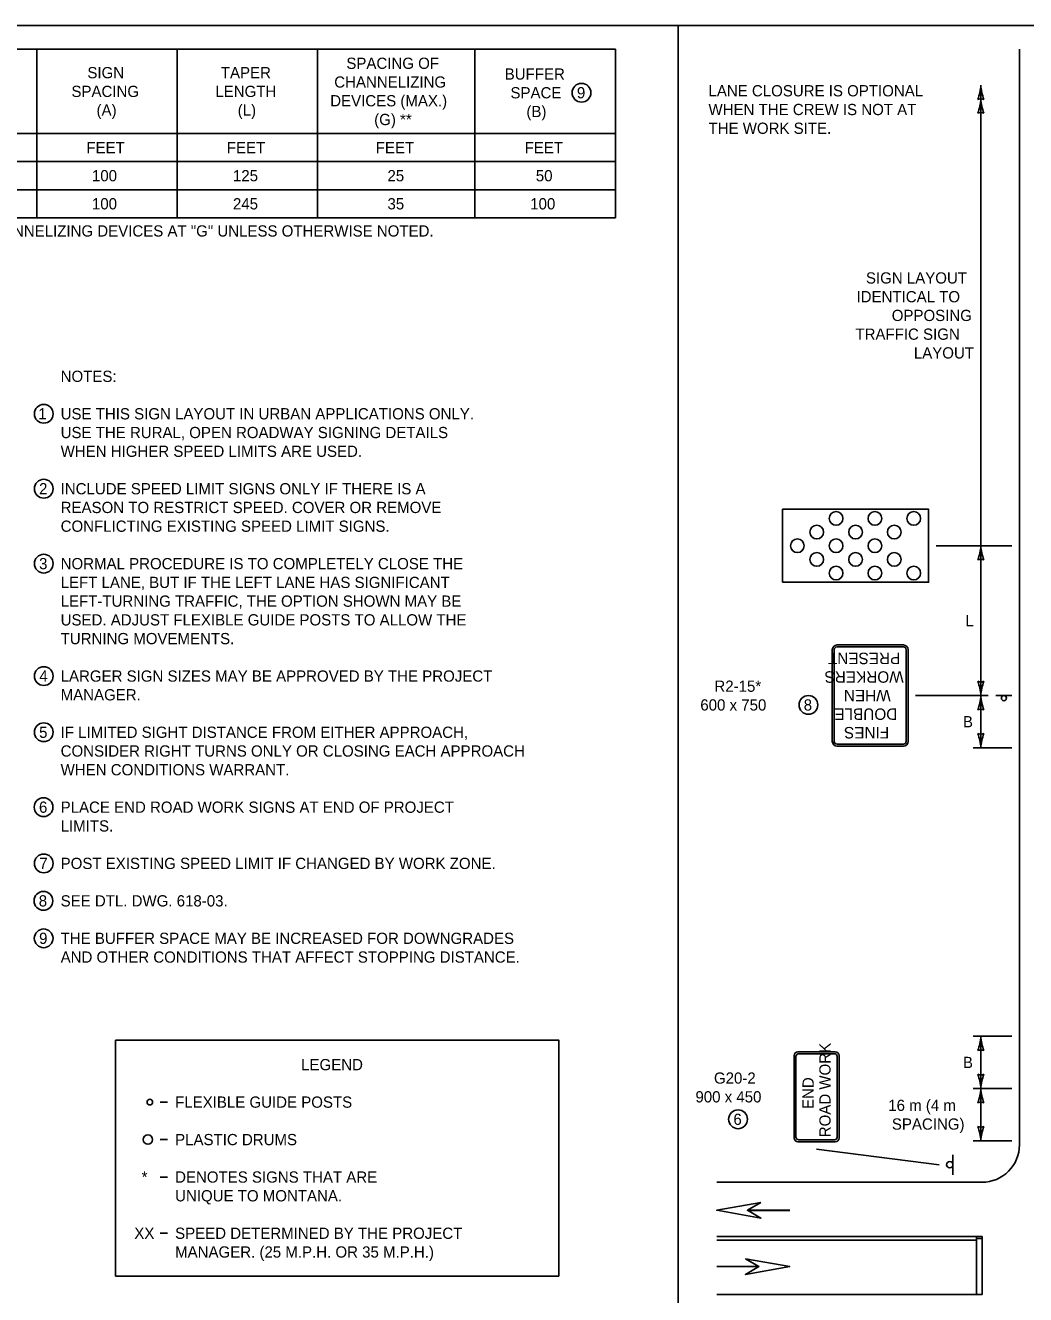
# Model space of a CAD drawing. Extents: x 49991.4 to 50021, y 49987.6 to 50011.4.
# Drawn here: x 50004.58 to 50009.92, y 49992.22 to 49999 of the extents above; entities that cross this region are included whole.
import ezdxf

# ---------------------------------------------------------------- set-up
doc = ezdxf.new("R2010")
doc.units = 0
for name, color, linetype in [('Level 1', 7, 'Continuous'), ('Level 2', 7, 'Continuous'), ('Level 3', 7, 'Continuous')]:
    doc.layers.add(name, color=color, linetype=linetype)

msp = doc.modelspace()

# ---------------------------------------------------------------- linework, layer by layer
at = {"layer": 'Level 1'}
for p, q in [((50008.0668, 49998.9992), (50008.0668, 49987.7988)), ((50009.889, 49993.024), (50009.889, 49998.8719)), ((50008.915, 49995.6917), (50009.2694, 49995.6917)), ((50008.915, 49995.6812), (50009.2694, 49995.6812)), ((50008.8896, 49995.177), (50008.8896, 49995.6664)), ((50008.9002, 49995.177), (50008.9002, 49995.6664)), ((50009.2842, 49995.6664), (50009.2842, 49995.177)), ((50009.2947, 49995.6664), (50009.2947, 49995.177)), ((50009.7626, 49995.4217), (50009.849, 49995.4217)), ((50009.2694, 49995.1622), (50008.915, 49995.1622)), ((50009.2694, 49995.1517), (50008.915, 49995.1517)), ((50009.0922, 49995.1517), (50009.0922, 49995.1517)), ((50008.7057, 49993.52), (50008.9057, 49993.52)), ((50008.7107, 49993.51), (50008.9007, 49993.51)), ((50008.6857, 49993.5), (50008.6857, 49993.06)), ((50008.6957, 49993.495), (50008.6957, 49993.065)), ((50008.9157, 49993.495), (50008.9157, 49993.065)), ((50008.9258, 49993.4999), (50008.9258, 49993.0599)), ((50008.9057, 49993.04), (50008.7057, 49993.04)), ((50008.9007, 49993.05), (50008.7107, 49993.05)), ((50009.5339, 49992.9706), (50009.5339, 49992.864)), ((50009.689, 49992.824), (50008.2722, 49992.824)), ((50008.6623, 49992.6741), (50008.4364, 49992.6741)), ((50008.6623, 49992.6737), (50008.4364, 49992.6737)), ((50009.689, 49992.5341), (50008.2722, 49992.5341)), ((50009.659, 49992.5141), (50008.2722, 49992.5141)), ((50009.659, 49992.5341), (50009.659, 49992.224)), ((50009.659, 49992.5241), (50009.689, 49992.5241)), ((50009.689, 49992.5341), (50009.689, 49992.224)), ((50008.2722, 49992.3741), (50008.4981, 49992.3741)), ((50008.2722, 49992.3737), (50008.4981, 49992.3737)), ((50009.689, 49992.224), (50008.2722, 49992.224))]:
    msp.add_line(p, q, dxfattribs=at)
for points in [[(49999.3835, 49998.9992), (50016.7501, 49998.9992), (50016.7501, 49987.7988), (49999.3835, 49987.7988)], [(50008.6239, 49996.0267), (50009.4036, 49996.0267), (50009.4036, 49996.4167), (50008.6239, 49996.4167)], [(50008.6239, 49996.0267), (50009.4036, 49996.0267), (50009.4036, 49996.4167), (50008.6239, 49996.4167)], [(50008.5087, 49992.7157), (50008.2722, 49992.6741), (50008.5087, 49992.6321), (50008.4365, 49992.6741)], [(50008.4258, 49992.4157), (50008.6623, 49992.3741), (50008.4258, 49992.3321), (50008.498, 49992.3741)]]:
    msp.add_lwpolyline(points, close=True, dxfattribs=at)
for points in [[(50009.689, 49992.5341), (50009.659, 49992.5341), (50009.659, 49992.5241), (50009.689, 49992.5241), (50009.689, 49992.5341)], [(50009.659, 49992.224), (50009.689, 49992.224), (50009.689, 49992.5241), (50009.659, 49992.5241), (50009.659, 49992.224)]]:
    msp.add_lwpolyline(points, dxfattribs=at)
for centre, radius in [((50008.91, 49996.3677), 0.0366), ((50008.91, 49996.3677), 0.0366), ((50009.1171, 49996.3677), 0.0366), ((50009.1171, 49996.3677), 0.0366), ((50009.3243, 49996.3677), 0.0366), ((50009.3243, 49996.3677), 0.0366), ((50008.8065, 49996.2946), 0.0366), ((50008.8065, 49996.2946), 0.0366), ((50009.0136, 49996.2946), 0.0366), ((50009.0136, 49996.2946), 0.0366), ((50009.2207, 49996.2946), 0.0366), ((50009.2207, 49996.2946), 0.0366), ((50008.7029, 49996.2215), 0.0366), ((50008.7029, 49996.2215), 0.0366), ((50008.91, 49996.2215), 0.0366), ((50008.91, 49996.2215), 0.0366), ((50009.1171, 49996.2215), 0.0366), ((50009.1171, 49996.2215), 0.0366), ((50008.8065, 49996.1484), 0.0366), ((50008.8065, 49996.1484), 0.0366), ((50009.0136, 49996.1484), 0.0366), ((50009.0136, 49996.1484), 0.0366), ((50009.2207, 49996.1484), 0.0366), ((50009.2207, 49996.1484), 0.0366), ((50008.91, 49996.0753), 0.0366), ((50008.91, 49996.0753), 0.0366), ((50009.1171, 49996.0753), 0.0366), ((50009.1171, 49996.0753), 0.0366), ((50009.3243, 49996.0753), 0.0366), ((50009.3243, 49996.0753), 0.0366), ((50009.8059, 49995.4081), 0.0137), ((50005.2457, 49993.2516), 0.015), ((50005.2357, 49993.0516), 0.025), ((50009.5171, 49992.9173), 0.0169)]:
    msp.add_circle(centre, radius, dxfattribs=at)
for centre, radius, start, end in [((50008.915, 49995.6664), 0.0253, 90, 180), ((50008.915, 49995.6664), 0.0148, 90, 180), ((50009.2694, 49995.6664), 0.0253, 360, 90), ((50009.2694, 49995.6664), 0.0148, 360, 90), ((50008.915, 49995.177), 0.0253, 180, 270), ((50008.915, 49995.177), 0.0148, 180, 270), ((50009.2694, 49995.177), 0.0148, 270, 360), ((50009.2694, 49995.177), 0.0253, 270, 360), ((50008.7057, 49993.5), 0.02, 90, 180), ((50008.7107, 49993.495), 0.015, 90, 180), ((50008.9007, 49993.495), 0.015, 360, 90), ((50008.9057, 49993.4999), 0.02, 360, 90), ((50005.2357, 49993.0516), 0.025, 360, 180), ((50005.2357, 49993.0516), 0.025, 180, 0), ((50008.7057, 49993.06), 0.02, 180, 270), ((50008.7107, 49993.065), 0.015, 180, 270), ((50008.9007, 49993.065), 0.015, 270, 360), ((50008.9057, 49993.0599), 0.02, 270, 360), ((50009.689, 49993.024), 0.2, 270, 0.00074)]:
    msp.add_arc(centre, radius, start, end, dxfattribs=at)
at = {"layer": 'Level 2'}
for p, q in [((50003.8015, 49998.8719), (50007.7315, 49998.8719)), ((50004.6415, 49998.8719), (50004.6415, 49997.9719)), ((50005.3915, 49998.8719), (50005.3915, 49997.9719)), ((50006.1415, 49998.8719), (50006.1415, 49997.9719)), ((50006.9815, 49998.8719), (50006.9815, 49997.9719)), ((50007.7315, 49998.8719), (50007.7315, 49997.9719)), ((50003.8015, 49998.4219), (50007.7315, 49998.4219)), ((50003.8015, 49998.2719), (50007.7315, 49998.2719)), ((50003.8015, 49998.1219), (50007.7315, 49998.1219)), ((50003.8015, 49997.9719), (50007.7315, 49997.9719)), ((50005.0629, 49992.3216), (50005.0629, 49993.5816)), ((50005.3407, 49993.2516), (50005.3007, 49993.2516)), ((50005.3007, 49993.0516), (50005.3407, 49993.0516)), ((50005.3407, 49992.8516), (50005.3007, 49992.8516)), ((50005.3407, 49992.5516), (50005.3007, 49992.5516)), ((50007.4297, 49992.3216), (50005.0629, 49992.3216))]:
    msp.add_line(p, q, dxfattribs=at)
msp.add_lwpolyline([(50005.0629, 49993.5816), (50007.4297, 49993.5816), (50007.4297, 49992.3216)], dxfattribs=at)
for centre in [(50007.5506, 49998.6397), (50004.6794, 49996.9259), (50004.6794, 49996.5259), (50004.6794, 49996.1259), (50004.6794, 49995.5259), (50008.762, 49995.3718), (50004.6794, 49995.2259), (50004.6783, 49994.8259), (50004.6794, 49994.5259), (50004.6776, 49994.3259), (50004.6789, 49994.1259), (50008.3863, 49993.1599)]:
    msp.add_circle(centre, 0.0501, dxfattribs=at)
at = {"layer": 'Level 3'}
for p, q in [((50009.6826, 49996.2217), (50009.6826, 49998.6802)), ((50009.4436, 49996.2217), (50009.849, 49996.2217)), ((50009.6826, 49995.4217), (50009.6826, 49996.2217)), ((50009.3347, 49995.4217), (50009.4587, 49995.4217)), ((50009.7226, 49995.4217), (50009.4587, 49995.4217)), ((50009.7226, 49995.4217), (50009.6426, 49995.4217)), ((50009.6826, 49995.1428), (50009.6826, 49995.4217)), ((50009.849, 49995.1428), (50009.6426, 49995.1428)), ((50009.849, 49993.6029), (50009.6426, 49993.6029)), ((50009.6826, 49993.3239), (50009.6826, 49993.6029)), ((50009.849, 49993.3239), (50009.6426, 49993.3239)), ((50009.6826, 49993.045), (50009.6826, 49993.3239)), ((50009.849, 49993.045), (50009.6426, 49993.045)), ((50008.8057, 49993), (50009.4602, 49992.9173))]:
    msp.add_line(p, q, dxfattribs=at)
for centre, radius, start, end in [((50009.4605, 49998.6894), 0.2223, 337.45601, 357.63952), ((50009.9153, 49998.6917), 0.233, 182.82731, 202.07716), ((50009.6826, 49998.552), 0.0548, 72.13882, 107.86118), ((50009.4605, 49998.616), 0.2223, 337.45601, 357.63952), ((50009.9153, 49998.6183), 0.233, 182.82731, 202.07716), ((50009.6826, 49998.4786), 0.0548, 72.13882, 107.86118), ((50009.4605, 49996.2309), 0.2223, 337.45601, 357.63952), ((50009.9153, 49996.2332), 0.233, 182.82731, 202.07716), ((50009.6826, 49996.0935), 0.0548, 72.13882, 107.86118), ((50009.6826, 49995.5499), 0.0548, 252.13882, 287.86118), ((50009.4499, 49995.4102), 0.233, 2.82731, 22.07716), ((50009.9048, 49995.4125), 0.2223, 157.45601, 177.63952), ((50009.4605, 49995.4309), 0.2223, 337.45601, 357.63952), ((50009.9153, 49995.4332), 0.233, 182.82731, 202.07716), ((50009.6826, 49995.2935), 0.0548, 72.13882, 107.86118), ((50009.6826, 49995.271), 0.0548, 252.13882, 287.86118), ((50009.4499, 49995.1313), 0.233, 2.82731, 22.07716), ((50009.9048, 49995.1336), 0.2223, 157.45601, 177.63952), ((50009.4605, 49993.612), 0.2223, 337.45601, 357.63952), ((50009.9153, 49993.6144), 0.233, 182.82731, 202.07716), ((50009.6826, 49993.4746), 0.0548, 72.13882, 107.86118), ((50009.6826, 49993.4522), 0.0548, 252.13882, 287.86118), ((50009.4499, 49993.3125), 0.233, 2.82731, 22.07716), ((50009.9048, 49993.3148), 0.2223, 157.45601, 177.63952), ((50009.4605, 49993.3331), 0.2223, 337.45601, 357.63952), ((50009.9153, 49993.3354), 0.233, 182.82731, 202.07716), ((50009.6826, 49993.1957), 0.0548, 72.13882, 107.86118), ((50009.6826, 49993.1733), 0.0548, 252.13882, 287.86118), ((50009.4499, 49993.0335), 0.233, 2.82731, 22.07716), ((50009.9048, 49993.0359), 0.2223, 157.45601, 177.63952)]:
    msp.add_arc(centre, radius, start, end, dxfattribs=at)

# ---------------------------------------------------------------- texts
at = {"layer": 'Level 1'}
for s, height, rotation, p in [('PRESENT', 0.06118, 180, (50009.2526, 49995.6506)), ('WORKERS', 0.06118, 180, (50009.2707, 49995.5514)), ('WHEN', 0.06118, 180, (50009.2013, 49995.4523)), ('DOUBLE', 0.06118, 180, (50009.2368, 49995.3531)), ('FINES', 0.06118, 180, (50009.1933, 49995.254)), ('ROAD WORK', 0.06, 90, (50008.8804, 49993.0641)), ('END', 0.06, 90, (50008.7904, 49993.2148))]:
    msp.add_text(s, height=height, rotation=rotation, dxfattribs=at).set_placement(p)
at = {"layer": 'Level 2'}
for s, height, p in [('SPACING OF', 0.06, (50006.295, 49998.7669)), ('SIGN', 0.06, (50004.9122, 49998.7169)), ('TAPER', 0.06, (50005.6248, 49998.7169)), ('CHANNELIZING', 0.06, (50006.2303, 49998.6669)), ('BUFFER', 0.06, (50007.1405, 49998.7096)), ('SPACING', 0.06, (50004.8271, 49998.6169)), ('LENGTH', 0.06, (50005.5956, 49998.6169)), ('SPACE', 0.06, (50007.1713, 49998.6096)), ('9', 0.06, (50007.526, 49998.6097)), ('LANE CLOSURE IS OPTIONAL', 0.06, (50008.2286, 49998.6202)), ('DEVICES (MAX.)', 0.06, (50006.2089, 49998.5669)), ('(A)', 0.06, (50004.9612, 49998.5169)), ('(L)', 0.06, (50005.7149, 49998.5169)), ('(G) **', 0.06, (50006.4436, 49998.4669)), ('(B)', 0.06, (50007.2564, 49998.5096)), ('WHEN THE CREW IS NOT AT', 0.06, (50008.2286, 49998.5202)), ('THE WORK SITE.', 0.06, (50008.2286, 49998.4202)), ('FEET', 0.06, (50004.9069, 49998.3169)), ('FEET', 0.06, (50005.6569, 49998.3169)), ('FEET', 0.06, (50006.4519, 49998.3169)), ('FEET', 0.06, (50007.2469, 49998.3169)), ('100', 0.06, (50004.9366, 49998.1669)), ('125', 0.06, (50005.6895, 49998.1669)), ('25', 0.06, (50006.5145, 49998.1669)), ('50', 0.06, (50007.3066, 49998.1669)), ('100', 0.06, (50004.9366, 49998.0169)), ('245', 0.06, (50005.6895, 49998.0169)), ('35', 0.06, (50006.5145, 49998.0169)), ('100', 0.06, (50007.2766, 49998.0169)), ('** SPACE ALL CHANNELIZING DEVICES AT "G" UNLESS OTHERWISE NOTED.', 0.06, (50003.8015, 49997.8719)), ('SIGN LAYOUT', 0.06, (50009.0692, 49997.621)), ('IDENTICAL TO', 0.06, (50009.0189, 49997.521)), ('OPPOSING', 0.06, (50009.207, 49997.421)), ('TRAFFIC SIGN', 0.06, (50009.0131, 49997.321)), ('LAYOUT', 0.06, (50009.3251, 49997.221)), ('NOTES:', 0.06, (50004.7695, 49997.0959)), ('1', 0.06, (50004.6502, 49996.896)), ('USE THIS SIGN LAYOUT IN URBAN APPLICATIONS ONLY.', 0.06, (50004.7695, 49996.8959)), ('USE THE RURAL, OPEN ROADWAY SIGNING DETAILS', 0.06, (50004.7695, 49996.7959)), ('WHEN HIGHER SPEED LIMITS ARE USED.', 0.06, (50004.7695, 49996.6959)), ('2', 0.06, (50004.6543, 49996.4959)), ('INCLUDE SPEED LIMIT SIGNS ONLY IF THERE IS A', 0.06, (50004.7695, 49996.4959)), ('REASON TO RESTRICT SPEED. COVER OR REMOVE', 0.06, (50004.7695, 49996.3959)), ('CONFLICTING EXISTING SPEED LIMIT SIGNS.', 0.06, (50004.7695, 49996.2959)), ('3', 0.06, (50004.6542, 49996.0959)), ('NORMAL PROCEDURE IS TO COMPLETELY CLOSE THE', 0.06, (50004.7695, 49996.0959)), ('LEFT LANE, BUT IF THE LEFT LANE HAS SIGNIFICANT ', 0.06, (50004.7695, 49995.9959)), ('LEFT-TURNING TRAFFIC, THE OPTION SHOWN MAY BE', 0.06, (50004.7695, 49995.8959)), ('USED. ADJUST FLEXIBLE GUIDE POSTS TO ALLOW THE ', 0.06, (50004.7695, 49995.7959)), ('L', 0.06, (50009.6002, 49995.7917)), ('TURNING MOVEMENTS.', 0.06, (50004.7695, 49995.6959)), ('4', 0.06, (50004.6555, 49995.4959)), ('LARGER SIGN SIZES MAY BE APPROVED BY THE PROJECT', 0.06, (50004.7695, 49995.4959)), ('R2-15*', 0.06, (50008.2601, 49995.4418)), ('MANAGER.', 0.06, (50004.7695, 49995.3959)), ('600 x 750', 0.06, (50008.1849, 49995.3418)), ('8', 0.06, (50008.737, 49995.3418)), ('B', 0.06, (50009.5871, 49995.2522)), ('5', 0.06, (50004.6545, 49995.1959)), ('IF LIMITED SIGHT DISTANCE FROM EITHER APPROACH,', 0.06, (50004.7695, 49995.1959)), ('CONSIDER RIGHT TURNS ONLY OR CLOSING EACH APPROACH', 0.06, (50004.7695, 49995.0959)), ('WHEN CONDITIONS WARRANT.', 0.06, (50004.7695, 49994.9959)), ('6', 0.06, (50004.6538, 49994.7959)), ('PLACE END ROAD WORK SIGNS AT END OF PROJECT', 0.06, (50004.7695, 49994.7959)), ('LIMITS.', 0.06, (50004.7695, 49994.6959)), ('7', 0.06, (50004.6556, 49994.4959)), ('POST EXISTING SPEED LIMIT IF CHANGED BY WORK ZONE.', 0.06, (50004.7695, 49994.4959)), ('8', 0.06, (50004.6526, 49994.2959)), ('SEE DTL. DWG. 618-03.', 0.06, (50004.7695, 49994.2959)), ('9', 0.06, (50004.6544, 49994.0959)), ('THE BUFFER SPACE MAY BE INCREASED FOR DOWNGRADES ', 0.06, (50004.7695, 49994.0959)), ('AND OTHER CONDITIONS THAT AFFECT STOPPING DISTANCE. ', 0.06, (50004.7695, 49993.9959)), ('LEGEND', 0.06, (50006.0536, 49993.4216)), ('B', 0.06, (50009.5871, 49993.4334)), ('G20-2', 0.06, (50008.2577, 49993.35)), ('900 x 450', 0.06, (50008.1588, 49993.25)), ('FLEXIBLE GUIDE POSTS', 0.06, (50005.3807, 49993.2216)), ('16 m (4 m ', 0.06, (50009.1884, 49993.2045)), ('6', 0.06, (50008.3618, 49993.1299)), ('SPACING)', 0.06, (50009.2077, 49993.1045)), ('PLASTIC DRUMS', 0.06, (50005.3807, 49993.0216)), ('*', 0.0601, (50005.202, 49992.8215)), ('DENOTES SIGNS THAT ARE', 0.06, (50005.3807, 49992.8216)), ('UNIQUE TO MONTANA.', 0.06, (50005.3807, 49992.7216)), ('XX', 0.06, (50005.1629, 49992.5216)), ('SPEED DETERMINED BY THE PROJECT', 0.06, (50005.3807, 49992.5216)), ('MANAGER. (25 M.P.H. OR 35 M.P.H.)', 0.06, (50005.3807, 49992.4216))]:
    msp.add_text(s, height=height, dxfattribs=at).set_placement(p)

doc.saveas('drawing.dxf')
